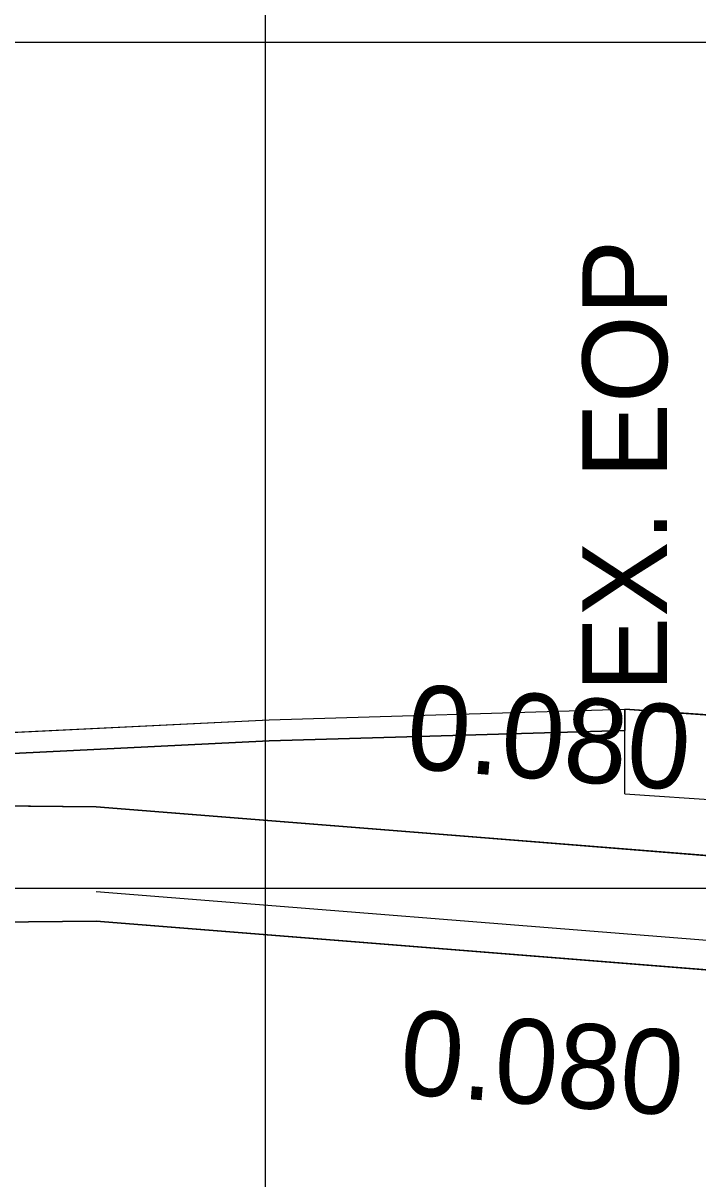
# Model space of a CAD drawing. Extents: x 1131015 to 1136271, y 133453 to 174329.
# Drawn here: x 1132327.59 to 1132335.56, y 158674.22 to 158687.88 of the extents above; entities that cross this region are included whole.
import ezdxf

# ---------------------------------------------------------------- set-up
doc = ezdxf.new("R2010")
doc.units = 0
for name, color, linetype in [('DESIGN - EARTHWORK - Shapes', 7, 'Continuous'), ('DESIGN - PUBLIC HEARING - Shapes', 7, 'Continuous'), ('DESIGN - SHEET - Linework', 7, 'Continuous'), ('DESIGN - TRANSPORTATION - Proposed Layout Patterning', 7, 'Continuous'), ('DESIGN - TYPICAL - Finished Grade and Subgrade', 7, 'Continuous'), ('DESIGN - TYPICAL - Finished Grade Slopes Text', 7, 'Continuous'), ('DESIGN - TYPICAL - Subgrade Cross Slope Text', 7, 'Continuous'), ('SURVEY - GROUND - Bottom of Topsoil Layer', 7, 'Continuous'), ('SURVEY - GROUND - Existing Pavement Layer', 7, 'Continuous'), ('SURVEY - GROUND - Existing Pavement Text', 7, 'Continuous'), ('SURVEY - GROUND - Top of Ground', 7, 'Continuous')]:
    doc.layers.add(name, color=color, linetype=linetype)

msp = doc.modelspace()

# ---------------------------------------------------------------- linework, layer by layer
at = {"layer": 'DESIGN - EARTHWORK - Shapes'}
for points in [[(1132322.456, 158678.678), (1132318.777, 158677.758), (1132307.208, 158676.76), (1132306.612, 158676.959), (1132319.89, 158678.104), (1132323.01, 158678.82), (1132326.111, 158679.433), (1132330.497, 158679.646), (1132334.7, 158679.771), (1132334.7, 158679.521), (1132330.497, 158679.396), (1132326.111, 158679.183), (1132323.503, 158678.667)], [(1132322.456, 158678.678), (1132318.777, 158677.758), (1132307.208, 158676.76), (1132306.612, 158676.959), (1132319.89, 158678.104), (1132323.01, 158678.82), (1132326.111, 158679.433), (1132330.497, 158679.646), (1132334.7, 158679.771), (1132334.7, 158679.521), (1132330.497, 158679.396), (1132326.111, 158679.183), (1132323.503, 158678.667)], [(1132322.456, 158678.678), (1132318.777, 158677.758), (1132307.208, 158676.76), (1132306.612, 158676.959), (1132319.89, 158678.104), (1132323.01, 158678.82), (1132326.111, 158679.433), (1132330.497, 158679.646), (1132334.7, 158679.771), (1132334.7, 158679.521), (1132330.497, 158679.396), (1132326.111, 158679.183), (1132323.503, 158678.667)], [(1132322.456, 158678.678), (1132318.777, 158677.758), (1132307.208, 158676.76), (1132306.612, 158676.959), (1132319.89, 158678.104), (1132323.01, 158678.82), (1132326.111, 158679.433), (1132330.497, 158679.646), (1132334.7, 158679.771), (1132334.7, 158679.521), (1132330.497, 158679.396), (1132326.111, 158679.183), (1132323.503, 158678.667)], [(1132322.456, 158678.678), (1132318.777, 158677.758), (1132307.208, 158676.76), (1132306.612, 158676.959), (1132319.89, 158678.104), (1132323.01, 158678.82), (1132326.111, 158679.433), (1132330.497, 158679.646), (1132334.7, 158679.771), (1132334.7, 158679.521), (1132330.497, 158679.396), (1132326.111, 158679.183), (1132323.503, 158678.667)], [(1132322.456, 158678.678), (1132318.777, 158677.758), (1132307.208, 158676.76), (1132306.612, 158676.959), (1132319.89, 158678.104), (1132323.01, 158678.82), (1132326.111, 158679.433), (1132330.497, 158679.646), (1132334.7, 158679.771), (1132334.7, 158679.521), (1132330.497, 158679.396), (1132326.111, 158679.183), (1132323.503, 158678.667)], [(1132322.456, 158678.678), (1132318.777, 158677.758), (1132307.208, 158676.76), (1132306.612, 158676.959), (1132319.89, 158678.104), (1132323.01, 158678.82), (1132326.111, 158679.433), (1132330.497, 158679.646), (1132334.7, 158679.771), (1132334.7, 158679.521), (1132330.497, 158679.396), (1132326.111, 158679.183), (1132323.503, 158678.667)], [(1132322.456, 158678.678), (1132318.777, 158677.758), (1132307.208, 158676.76), (1132306.612, 158676.959), (1132319.89, 158678.104), (1132323.01, 158678.82), (1132326.111, 158679.433), (1132330.497, 158679.646), (1132334.7, 158679.771), (1132334.7, 158679.521), (1132330.497, 158679.396), (1132326.111, 158679.183), (1132323.503, 158678.667)], [(1132322.456, 158678.678), (1132318.777, 158677.758), (1132307.208, 158676.76), (1132306.612, 158676.959), (1132319.89, 158678.104), (1132323.01, 158678.82), (1132326.111, 158679.433), (1132330.497, 158679.646), (1132334.7, 158679.771), (1132334.7, 158679.521), (1132330.497, 158679.396), (1132326.111, 158679.183), (1132323.503, 158678.667)], [(1132330.497, 158679.646), (1132334.7, 158679.771), (1132334.7, 158679.521), (1132330.497, 158679.396), (1132326.111, 158679.183), (1132323.503, 158678.667), (1132322.456, 158678.678), (1132318.777, 158677.758), (1132307.208, 158676.76), (1132306.612, 158676.959), (1132319.89, 158678.104), (1132323.01, 158678.82), (1132326.111, 158679.433)], [(1132330.497, 158679.646), (1132334.7, 158679.771), (1132334.7, 158679.521), (1132330.497, 158679.396), (1132326.111, 158679.183), (1132323.503, 158678.667), (1132322.456, 158678.678), (1132318.777, 158677.758), (1132307.208, 158676.76), (1132306.612, 158676.959), (1132319.89, 158678.104), (1132323.01, 158678.82), (1132326.111, 158679.433)], [(1132330.497, 158679.646), (1132334.7, 158679.771), (1132334.7, 158679.521), (1132330.497, 158679.396), (1132326.111, 158679.183), (1132323.503, 158678.667), (1132322.456, 158678.678), (1132318.777, 158677.758), (1132307.208, 158676.76), (1132306.612, 158676.959), (1132319.89, 158678.104), (1132323.01, 158678.82), (1132326.111, 158679.433)], [(1132330.497, 158679.646), (1132334.7, 158679.771), (1132334.7, 158679.521), (1132330.497, 158679.396), (1132326.111, 158679.183), (1132323.503, 158678.667), (1132322.456, 158678.678), (1132318.777, 158677.758), (1132307.208, 158676.76), (1132306.612, 158676.959), (1132319.89, 158678.104), (1132323.01, 158678.82), (1132326.111, 158679.433)], [(1132330.497, 158679.646), (1132334.7, 158679.771), (1132334.7, 158679.521), (1132330.497, 158679.396), (1132326.111, 158679.183), (1132323.503, 158678.667), (1132322.456, 158678.678), (1132318.777, 158677.758), (1132307.208, 158676.76), (1132306.612, 158676.959), (1132319.89, 158678.104), (1132323.01, 158678.82), (1132326.111, 158679.433)], [(1132330.497, 158679.646), (1132334.7, 158679.771), (1132334.7, 158679.521), (1132330.497, 158679.396), (1132326.111, 158679.183), (1132323.503, 158678.667), (1132322.456, 158678.678), (1132318.777, 158677.758), (1132307.208, 158676.76), (1132306.612, 158676.959), (1132319.89, 158678.104), (1132323.01, 158678.82), (1132326.111, 158679.433)], [(1132330.497, 158679.646), (1132334.7, 158679.771), (1132334.7, 158679.521), (1132330.497, 158679.396), (1132326.111, 158679.183), (1132323.503, 158678.667), (1132322.456, 158678.678), (1132318.777, 158677.758), (1132307.208, 158676.76), (1132306.612, 158676.959), (1132319.89, 158678.104), (1132323.01, 158678.82), (1132326.111, 158679.433)], [(1132330.497, 158679.646), (1132334.7, 158679.771), (1132334.7, 158679.521), (1132330.497, 158679.396), (1132326.111, 158679.183), (1132323.503, 158678.667), (1132322.456, 158678.678), (1132318.777, 158677.758), (1132307.208, 158676.76), (1132306.612, 158676.959), (1132319.89, 158678.104), (1132323.01, 158678.82), (1132326.111, 158679.433)], [(1132330.497, 158679.646), (1132334.7, 158679.771), (1132334.7, 158679.521), (1132330.497, 158679.396), (1132326.111, 158679.183), (1132323.503, 158678.667), (1132322.456, 158678.678), (1132318.777, 158677.758), (1132307.208, 158676.76), (1132307.035, 158676.818), (1132306.612, 158676.959), (1132319.89, 158678.104), (1132323.01, 158678.82), (1132326.111, 158679.433)], [(1132356.456, 158675.028), (1132358.456, 158674.868), (1132361.384, 158674.633), (1132369.325, 158673.998), (1132373.384, 158672.983), (1132369.399, 158668.998), (1132315.016, 158668.998), (1132315.016, 158674.96), (1132315.016, 158676.818), (1132316.331, 158677.146), (1132322.456, 158677.208), (1132324.456, 158677.228), (1132328.456, 158677.268), (1132332.456, 158676.948), (1132340.456, 158676.308), (1132348.456, 158675.668), (1132352.456, 158675.348)]]:
    msp.add_lwpolyline(points, close=True, dxfattribs=at)
for points in [[(1132336.547, 158679.645), (1132334.7, 158679.771), (1132334.7, 158679.521), (1132330.497, 158679.396), (1132326.111, 158679.183), (1132323.503, 158678.667), (1132324.456, 158678.658), (1132328.456, 158678.618), (1132332.456, 158678.298), (1132340.456, 158677.658)], [(1132336.547, 158679.645), (1132334.7, 158679.771), (1132334.7, 158679.521), (1132330.497, 158679.396), (1132326.111, 158679.183), (1132323.503, 158678.667), (1132324.456, 158678.658), (1132328.456, 158678.618), (1132332.456, 158678.298), (1132340.456, 158677.658)], [(1132340.456, 158677.658), (1132332.456, 158678.298), (1132328.456, 158678.618), (1132324.456, 158678.658), (1132323.503, 158678.667), (1132326.111, 158679.183), (1132330.497, 158679.396), (1132334.7, 158679.521), (1132334.7, 158679.771), (1132336.547, 158679.645)], [(1132336.547, 158679.645), (1132334.7, 158679.771), (1132334.7, 158679.521), (1132330.497, 158679.396), (1132326.111, 158679.183), (1132323.503, 158678.667), (1132324.456, 158678.658), (1132328.456, 158678.618), (1132332.456, 158678.298), (1132340.456, 158677.658)], [(1132336.547, 158679.645), (1132334.7, 158679.771), (1132334.7, 158679.521), (1132330.497, 158679.396), (1132326.111, 158679.183), (1132323.503, 158678.667), (1132324.456, 158678.658), (1132328.456, 158678.618), (1132332.456, 158678.298), (1132340.456, 158677.658)], [(1132336.547, 158679.645), (1132334.7, 158679.771), (1132334.7, 158679.521), (1132330.497, 158679.396), (1132326.111, 158679.183), (1132323.503, 158678.667), (1132324.456, 158678.658), (1132328.456, 158678.618), (1132332.456, 158678.298), (1132340.456, 158677.658)], [(1132336.547, 158679.645), (1132334.7, 158679.771), (1132334.7, 158679.521), (1132330.497, 158679.396), (1132326.111, 158679.183), (1132323.503, 158678.667), (1132324.456, 158678.658), (1132328.456, 158678.618), (1132332.456, 158678.298), (1132340.456, 158677.658)], [(1132336.547, 158679.645), (1132334.7, 158679.771), (1132334.7, 158679.521), (1132330.497, 158679.396), (1132326.111, 158679.183), (1132323.503, 158678.667), (1132324.456, 158678.658), (1132328.456, 158678.618), (1132332.456, 158678.298), (1132340.456, 158677.658)], [(1132336.547, 158679.645), (1132334.7, 158679.771), (1132334.7, 158679.521), (1132330.497, 158679.396), (1132326.111, 158679.183), (1132323.503, 158678.667), (1132324.456, 158678.658), (1132328.456, 158678.618), (1132332.456, 158678.298), (1132340.456, 158677.658)], [(1132336.547, 158679.645), (1132334.7, 158679.771), (1132334.7, 158679.521), (1132330.497, 158679.396), (1132326.111, 158679.183), (1132323.503, 158678.667), (1132324.456, 158678.658), (1132328.456, 158678.618), (1132332.456, 158678.298), (1132340.456, 158677.658)], [(1132336.547, 158679.645), (1132334.7, 158679.771), (1132334.7, 158679.521), (1132330.497, 158679.396), (1132326.111, 158679.183), (1132323.503, 158678.667), (1132324.456, 158678.658), (1132328.456, 158678.618), (1132332.456, 158678.298), (1132340.456, 158677.658)], [(1132340.456, 158677.658), (1132332.456, 158678.298), (1132328.456, 158678.618), (1132324.456, 158678.658), (1132323.503, 158678.667), (1132326.111, 158679.183), (1132330.497, 158679.396), (1132334.7, 158679.521), (1132334.7, 158679.771), (1132336.547, 158679.645)], [(1132336.547, 158679.645), (1132334.7, 158679.771), (1132334.7, 158679.521), (1132330.497, 158679.396), (1132326.111, 158679.183), (1132323.503, 158678.667), (1132324.456, 158678.658), (1132328.456, 158678.618), (1132332.456, 158678.298), (1132340.456, 158677.658)], [(1132336.547, 158679.645), (1132334.7, 158679.771), (1132334.7, 158679.521), (1132330.497, 158679.396), (1132326.111, 158679.183), (1132323.503, 158678.667), (1132324.456, 158678.658), (1132328.456, 158678.618), (1132332.456, 158678.298), (1132340.456, 158677.658)], [(1132336.547, 158679.645), (1132334.7, 158679.771), (1132334.7, 158679.521), (1132330.497, 158679.396), (1132326.111, 158679.183), (1132323.503, 158678.667), (1132324.456, 158678.658), (1132328.456, 158678.618), (1132332.456, 158678.298), (1132340.456, 158677.658)], [(1132336.547, 158679.645), (1132334.7, 158679.771), (1132334.7, 158679.521), (1132330.497, 158679.396), (1132326.111, 158679.183), (1132323.503, 158678.667), (1132324.456, 158678.658), (1132328.456, 158678.618), (1132332.456, 158678.298), (1132340.456, 158677.658)], [(1132336.547, 158679.645), (1132334.7, 158679.771), (1132334.7, 158679.521), (1132330.497, 158679.396), (1132326.111, 158679.183), (1132323.503, 158678.667), (1132324.456, 158678.658), (1132328.456, 158678.618), (1132332.456, 158678.298), (1132340.456, 158677.658)], [(1132340.456, 158677.658), (1132332.456, 158678.298), (1132328.456, 158678.618), (1132324.456, 158678.658), (1132323.503, 158678.667), (1132326.111, 158679.183), (1132330.497, 158679.396), (1132334.7, 158679.521), (1132334.7, 158679.771), (1132336.547, 158679.645)], [(1132340.456, 158676.308), (1132332.456, 158676.948), (1132328.456, 158677.268), (1132324.456, 158677.228), (1132322.456, 158677.208), (1132316.331, 158677.146), (1132318.777, 158677.758), (1132319.89, 158677.854), (1132323.01, 158678.57), (1132323.503, 158678.667), (1132324.456, 158678.658), (1132328.456, 158678.618), (1132332.456, 158678.298), (1132340.456, 158677.658)], [(1132340.456, 158676.308), (1132332.456, 158676.948), (1132328.456, 158677.268), (1132324.456, 158677.228), (1132322.456, 158677.208), (1132316.331, 158677.146), (1132318.777, 158677.758), (1132319.89, 158677.854), (1132323.01, 158678.57), (1132323.503, 158678.667), (1132324.456, 158678.658), (1132328.456, 158678.618), (1132332.456, 158678.298), (1132340.456, 158677.658)], [(1132340.456, 158676.308), (1132332.456, 158676.948), (1132328.456, 158677.268), (1132324.456, 158677.228), (1132322.456, 158677.208), (1132316.331, 158677.146), (1132318.777, 158677.758), (1132319.89, 158677.854), (1132323.01, 158678.57), (1132323.503, 158678.667), (1132324.456, 158678.658), (1132328.456, 158678.618), (1132332.456, 158678.298), (1132340.456, 158677.658)], [(1132340.456, 158676.308), (1132332.456, 158676.948), (1132328.456, 158677.268), (1132324.456, 158677.228), (1132322.456, 158677.208), (1132316.331, 158677.146), (1132318.777, 158677.758), (1132319.89, 158677.854), (1132323.01, 158678.57), (1132323.503, 158678.667), (1132324.456, 158678.658), (1132328.456, 158678.618), (1132332.456, 158678.298), (1132340.456, 158677.658)], [(1132340.456, 158676.308), (1132332.456, 158676.948), (1132328.456, 158677.268), (1132324.456, 158677.228), (1132322.456, 158677.208), (1132316.331, 158677.146), (1132318.777, 158677.758), (1132319.89, 158677.854), (1132323.01, 158678.57), (1132323.503, 158678.667), (1132324.456, 158678.658), (1132328.456, 158678.618), (1132332.456, 158678.298), (1132340.456, 158677.658)], [(1132340.456, 158676.308), (1132332.456, 158676.948), (1132328.456, 158677.268), (1132324.456, 158677.228), (1132322.456, 158677.208), (1132316.331, 158677.146), (1132318.777, 158677.758), (1132319.89, 158677.854), (1132323.01, 158678.57), (1132323.503, 158678.667), (1132324.456, 158678.658), (1132328.456, 158678.618), (1132332.456, 158678.298), (1132340.456, 158677.658)], [(1132340.456, 158676.308), (1132332.456, 158676.948), (1132328.456, 158677.268), (1132324.456, 158677.228), (1132322.456, 158677.208), (1132316.331, 158677.146), (1132318.777, 158677.758), (1132319.89, 158677.854), (1132323.01, 158678.57), (1132323.503, 158678.667), (1132324.456, 158678.658), (1132328.456, 158678.618), (1132332.456, 158678.298), (1132340.456, 158677.658)], [(1132340.456, 158676.308), (1132332.456, 158676.948), (1132328.456, 158677.268), (1132324.456, 158677.228), (1132322.456, 158677.208), (1132316.331, 158677.146), (1132318.777, 158677.758), (1132319.89, 158677.854), (1132323.01, 158678.57), (1132323.503, 158678.667), (1132324.456, 158678.658), (1132328.456, 158678.618), (1132332.456, 158678.298), (1132340.456, 158677.658)], [(1132340.456, 158676.308), (1132332.456, 158676.948), (1132328.456, 158677.268), (1132324.456, 158677.228), (1132322.456, 158677.208), (1132316.331, 158677.146), (1132318.777, 158677.758), (1132319.89, 158677.854), (1132323.01, 158678.57), (1132323.503, 158678.667), (1132324.456, 158678.658), (1132328.456, 158678.618), (1132332.456, 158678.298), (1132340.456, 158677.658)], [(1132340.456, 158676.308), (1132332.456, 158676.948), (1132328.456, 158677.268), (1132324.456, 158677.228), (1132322.456, 158677.208), (1132316.331, 158677.146), (1132318.777, 158677.758), (1132319.89, 158677.854), (1132323.01, 158678.57), (1132323.503, 158678.667), (1132324.456, 158678.658), (1132328.456, 158678.618), (1132332.456, 158678.298), (1132340.456, 158677.658)], [(1132340.456, 158676.308), (1132332.456, 158676.948), (1132328.456, 158677.268), (1132324.456, 158677.228), (1132322.456, 158677.208), (1132316.331, 158677.146), (1132318.777, 158677.758), (1132319.89, 158677.854), (1132323.01, 158678.57), (1132323.503, 158678.667), (1132324.456, 158678.658), (1132328.456, 158678.618), (1132332.456, 158678.298), (1132340.456, 158677.658)], [(1132340.456, 158676.308), (1132332.456, 158676.948), (1132328.456, 158677.268), (1132324.456, 158677.228), (1132322.456, 158677.208), (1132316.331, 158677.146), (1132318.777, 158677.758), (1132319.89, 158677.854), (1132323.01, 158678.57), (1132323.503, 158678.667), (1132324.456, 158678.658), (1132328.456, 158678.618), (1132332.456, 158678.298), (1132340.456, 158677.658)], [(1132340.456, 158676.308), (1132332.456, 158676.948), (1132328.456, 158677.268), (1132324.456, 158677.228), (1132322.456, 158677.208), (1132316.331, 158677.146), (1132318.777, 158677.758), (1132319.89, 158677.854), (1132323.01, 158678.57), (1132323.503, 158678.667), (1132324.456, 158678.658), (1132328.456, 158678.618), (1132332.456, 158678.298), (1132340.456, 158677.658)], [(1132340.456, 158676.308), (1132332.456, 158676.948), (1132328.456, 158677.268), (1132324.456, 158677.228), (1132322.456, 158677.208), (1132316.331, 158677.146), (1132318.777, 158677.758), (1132319.89, 158677.854), (1132323.01, 158678.57), (1132323.503, 158678.667), (1132324.456, 158678.658), (1132328.456, 158678.618), (1132332.456, 158678.298), (1132340.456, 158677.658)], [(1132340.456, 158676.308), (1132332.456, 158676.948), (1132328.456, 158677.268), (1132324.456, 158677.228), (1132322.456, 158677.208), (1132316.331, 158677.146), (1132318.777, 158677.758), (1132319.89, 158677.854), (1132323.01, 158678.57), (1132323.503, 158678.667), (1132324.456, 158678.658), (1132328.456, 158678.618), (1132332.456, 158678.298), (1132340.456, 158677.658)], [(1132340.456, 158676.308), (1132332.456, 158676.948), (1132328.456, 158677.268), (1132324.456, 158677.228), (1132322.456, 158677.208), (1132316.331, 158677.146), (1132318.777, 158677.758), (1132319.89, 158677.854), (1132323.01, 158678.57), (1132323.503, 158678.667), (1132324.456, 158678.658), (1132328.456, 158678.618), (1132332.456, 158678.298), (1132340.456, 158677.658)], [(1132340.456, 158676.308), (1132332.456, 158676.948), (1132328.456, 158677.268), (1132324.456, 158677.228), (1132322.456, 158677.208), (1132316.331, 158677.146), (1132318.777, 158677.758), (1132319.89, 158677.854), (1132323.01, 158678.57), (1132323.503, 158678.667), (1132324.456, 158678.658), (1132328.456, 158678.618), (1132332.456, 158678.298), (1132340.456, 158677.658)], [(1132340.456, 158677.658), (1132332.456, 158678.298), (1132328.456, 158678.618), (1132324.456, 158678.658), (1132323.503, 158678.667), (1132323.01, 158678.57), (1132319.89, 158677.854), (1132318.777, 158677.758), (1132316.331, 158677.146), (1132322.456, 158677.208), (1132324.456, 158677.228), (1132328.456, 158677.268), (1132332.456, 158676.948), (1132340.456, 158676.308)]]:
    msp.add_lwpolyline(points, dxfattribs=at)
at = {"layer": 'DESIGN - PUBLIC HEARING - Shapes'}
for p, q in [((1132340.456, 158677.658), (1132328.456, 158678.618)), ((1132340.456, 158677.658), (1132328.456, 158678.618)), ((1132340.456, 158677.658), (1132328.456, 158678.618)), ((1132340.456, 158677.658), (1132328.456, 158678.618)), ((1132340.456, 158677.658), (1132328.456, 158678.618)), ((1132328.456, 158677.618), (1132340.456, 158676.658)), ((1132328.456, 158677.618), (1132340.456, 158676.658)), ((1132328.456, 158677.618), (1132340.456, 158676.658)), ((1132328.456, 158677.618), (1132340.456, 158676.658)), ((1132328.456, 158677.618), (1132340.456, 158676.658))]:
    msp.add_line(p, q, dxfattribs=at)
at = {"layer": 'DESIGN - SHEET - Linework'}
for p, q in [((1132330.456, 158617.655), (1132330.456, 158827.655)), ((1132190.456, 158687.655), (1132490.456, 158687.655)), ((1132190.456, 158677.655), (1132490.456, 158677.655))]:
    msp.add_line(p, q, dxfattribs=at)
at = {"layer": 'DESIGN - TRANSPORTATION - Proposed Layout Patterning'}
msp.add_lwpolyline([(1132315.016, 158668.998), (1132315.016, 158676.818), (1132316.331, 158677.146), (1132328.456, 158677.268), (1132369.325, 158673.998), (1132373.384, 158672.983), (1132369.399, 158668.998)], close=True, dxfattribs=at)
at = {"layer": 'DESIGN - TYPICAL - Finished Grade and Subgrade'}
for p, q in [((1132328.456, 158678.618), (1132324.456, 158678.658)), ((1132332.456, 158678.298), (1132328.456, 158678.618)), ((1132332.456, 158678.298), (1132340.456, 158677.658)), ((1132328.456, 158677.268), (1132324.456, 158677.228)), ((1132332.456, 158676.948), (1132328.456, 158677.268)), ((1132340.456, 158676.308), (1132332.456, 158676.948))]:
    msp.add_line(p, q, dxfattribs=at)
at = {"layer": 'SURVEY - GROUND - Bottom of Topsoil Layer'}
for p, q in [((1132334.7, 158679.521), (1132334.7, 158679.771)), ((1132330.497, 158679.396), (1132334.7, 158679.521)), ((1132326.111, 158679.183), (1132330.497, 158679.396))]:
    msp.add_line(p, q, dxfattribs=at)
at = {"layer": 'SURVEY - GROUND - Existing Pavement Layer'}
for q in [(1132334.7, 158679.771), (1132336.547, 158678.645)]:
    msp.add_line((1132334.7, 158678.771), q, dxfattribs=at)
at = {"layer": 'SURVEY - GROUND - Top of Ground'}
for p, q in [((1132330.497, 158679.646), (1132334.7, 158679.771)), ((1132334.7, 158679.771), (1132336.547, 158679.645)), ((1132326.111, 158679.433), (1132330.497, 158679.646))]:
    msp.add_line(p, q, dxfattribs=at)

# ---------------------------------------------------------------- texts
at = {"layer": 'DESIGN - TYPICAL - Finished Grade Slopes Text'}
msp.add_text('0.080', height=1, rotation=355.4261, dxfattribs=at).set_placement((1132332.098, 158679.076))
at = {"layer": 'DESIGN - TYPICAL - Subgrade Cross Slope Text'}
msp.add_text('0.080', height=1, rotation=355.4261, dxfattribs=at).set_placement((1132332.018, 158675.229))
at = {"layer": 'SURVEY - GROUND - Existing Pavement Text'}
msp.add_text('EX. EOP', height=1, rotation=90, dxfattribs=at).set_placement((1132335.2, 158679.971))

doc.saveas('drawing.dxf')
